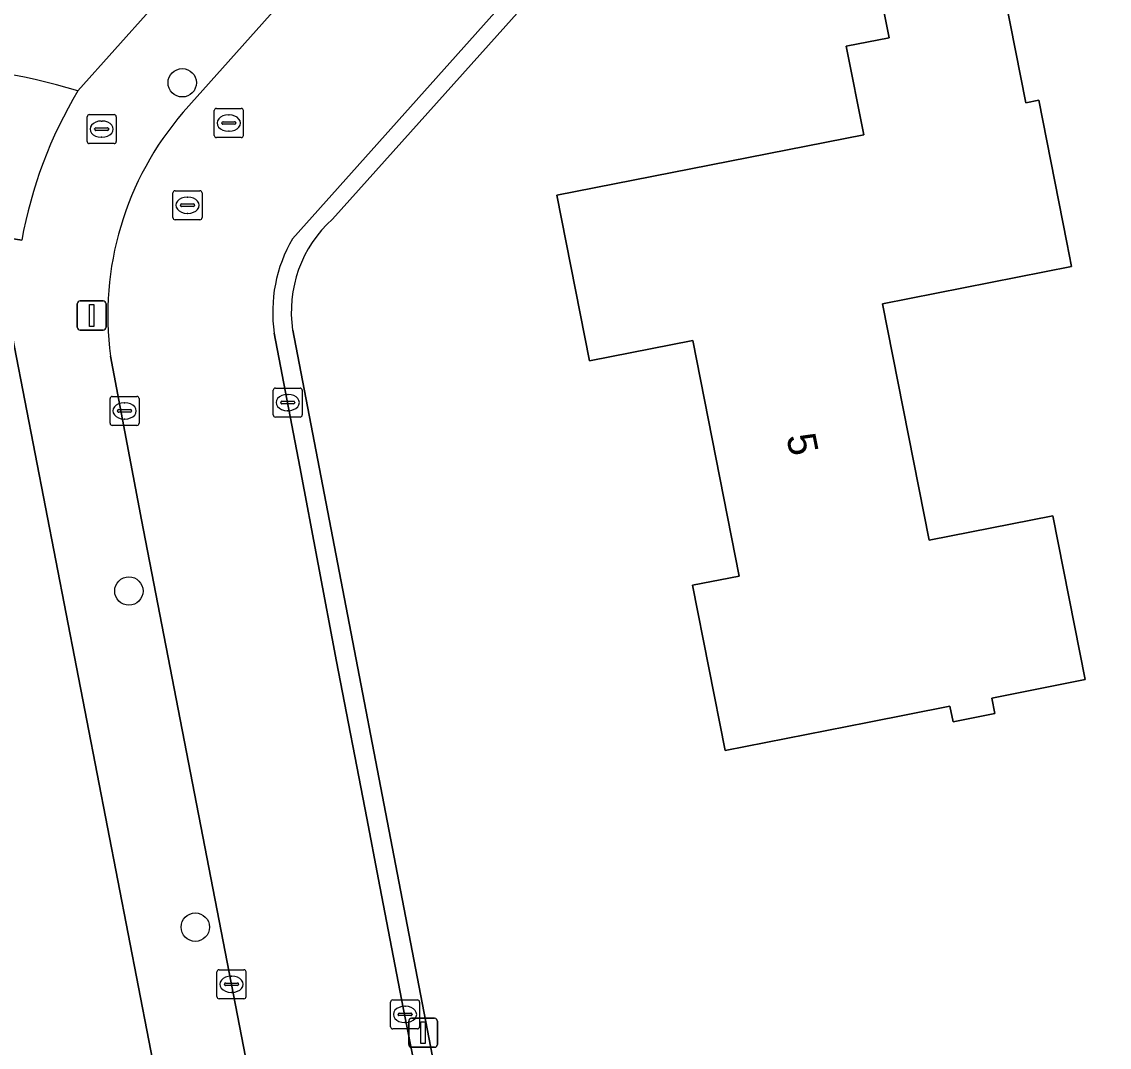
# Model space of a CAD drawing. Extents: x 157648 to 158502, y 379212 to 380938.
# Drawn here: x 158338.43 to 158375.88, y 380216.08 to 380251.41 of the extents above; entities that cross this region are included whole.
import ezdxf

# ---------------------------------------------------------------- set-up
doc = ezdxf.new("R2010")
doc.units = 0
for name, color, linetype in [('IMGEO_Boom', 7, 'Continuous'), ('IMGEO_Brandkraan', 7, 'Continuous'), ('IMGEO_Erf', 7, 'Continuous'), ('IMGEO_Kolk', 7, 'Continuous'), ('IMGEO_Lichtmast', 7, 'Continuous'), ('IMGEO_Pand', 7, 'Continuous'), ('IMGEO_Pand_nummerreeks', 7, 'Continuous'), ('IMGEO_Rijbaan_lokaal_open', 7, 'Continuous'), ('IMGEO_Rioolput', 7, 'Continuous'), ('IMGEO_Voetpad_open', 7, 'Continuous')]:
    doc.layers.add(name, color=color, linetype=linetype)

msp = doc.modelspace()

# ---------------------------------------------------------------- linework, layer by layer
at = {"layer": 'IMGEO_Boom'}
for centre in [(158343.956, 380249.306), (158342.119, 380231.798), (158344.405, 380220.221)]:
    msp.add_circle(centre, 0.489, dxfattribs=at)
at = {"layer": 'IMGEO_Brandkraan'}
for p, q in [((158340.681, 380247.283), (158340.681, 380248.135)), ((158340.756, 380248.209), (158341.608, 380248.209)), ((158341.169, 380247.989), (158341.194, 380247.989)), ((158341.682, 380248.135), (158341.682, 380247.283)), ((158340.94, 380247.703), (158340.94, 380247.715)), ((158341.378, 380247.666), (158340.98, 380247.666)), ((158340.983, 380247.752), (158341.381, 380247.752)), ((158341.424, 380247.715), (158341.424, 380247.703)), ((158341.608, 380247.209), (158340.756, 380247.209)), ((158341.192, 380247.429), (158341.167, 380247.429))]:
    msp.add_line(p, q, dxfattribs=at)
for points in [[(158340.681, 380247.283), (158340.681, 380248.135)], [(158340.756, 380248.209), (158341.608, 380248.209)], [(158341.682, 380248.135), (158341.682, 380247.283)], [(158341.608, 380247.209), (158340.756, 380247.209)]]:
    msp.add_lwpolyline(points, dxfattribs=at)
for centre, radius, start, end in [((158340.758, 380248.133), 0.0765, 91.552, 178.448), ((158340.758, 380248.133), 0.0765, 91.552, 178.448), ((158341.606, 380248.133), 0.0765, 1.552, 88.448), ((158341.606, 380248.133), 0.0765, 1.552, 88.448), ((158340.98, 380247.712), 0.0403, 85.8775, 175.7526), ((158340.977, 380247.702), 0.0366, 178.938, 274.7102), ((158341.381, 380247.709), 0.043, 264.8664, 352.4533), ((158341.385, 380247.714), 0.0386, 1.7309, 96.639), ((158340.758, 380247.285), 0.0765, 181.552, 268.448), ((158340.758, 380247.285), 0.0765, 181.552, 268.448), ((158341.606, 380247.285), 0.0765, 271.552, 358.448), ((158341.606, 380247.285), 0.0765, 271.552, 358.448)]:
    msp.add_arc(centre, radius, start, end, dxfattribs=at)
for centre, major_axis, ratio, start_param, end_param in [((158341.168, 380247.709), (-0.387, 0.002), 0.722429, 4.712389, 7.853982), ((158341.193, 380247.709), (-0.39, 0.002), 0.717154, 1.570796, 4.712389)]:
    msp.add_ellipse(centre, major_axis=major_axis, ratio=ratio, start_param=start_param, end_param=end_param, dxfattribs=at)
at = {"layer": 'IMGEO_Erf'}
for points in [[(158340.365, 380249.033), (158363.297, 380274.662)], [(158429.436, 380221.799), (158397.765, 380250), (158373.398, 380271.696), (158349.129, 380244.613)], [(158352.062, 380168.551), (158337.459, 380243.871)], [(158347.76, 380240.781), (158358.166, 380186.679), (158368.973, 380188.865), (158369.173, 380188.521), (158373.845, 380164.27), (158362.257, 380162.057), (158342.395, 380158.264)]]:
    msp.add_lwpolyline(points, dxfattribs=at)
msp.add_lwpolyline([(158368.072, 380241.691), (158369.676, 380233.548), (158373.945, 380234.39), (158375.057, 380228.746), (158371.841, 380228.112), (158371.947, 380227.576), (158370.505, 380227.29), (158370.398, 380227.828), (158367.562, 380227.27), (158362.656, 380226.303), (158361.534, 380232), (158363.14, 380232.316), (158361.541, 380240.433), (158357.982, 380239.732), (158356.859, 380245.434), (158367.426, 380247.516), (158366.825, 380250.563), (158368.299, 380250.854), (158367.832, 380253.223), (158371.947, 380254.034), (158373.014, 380248.617), (158373.454, 380248.704), (158374.42, 380243.799), (158374.583, 380242.974)], close=True, dxfattribs=at)
for centre, radius, start, end in [((158333, 380223.655), 26.425, 73.8176, 100.1183), ((158352.023, 380241.418), 4.311, 132.1775, 188.5034)]:
    msp.add_arc(centre, radius, start, end, dxfattribs=at)
at = {"layer": 'IMGEO_Kolk'}
for p, q in [((158347.088, 380237.864), (158347.088, 380238.716)), ((158347.163, 380238.79), (158348.015, 380238.79)), ((158347.576, 380238.57), (158347.601, 380238.57)), ((158348.089, 380238.716), (158348.089, 380237.864)), ((158341.469, 380237.577), (158341.469, 380238.429)), ((158341.544, 380238.503), (158342.396, 380238.503)), ((158341.957, 380238.283), (158341.982, 380238.283)), ((158342.47, 380238.429), (158342.47, 380237.577)), ((158347.347, 380238.284), (158347.347, 380238.296)), ((158347.785, 380238.247), (158347.387, 380238.247)), ((158347.39, 380238.333), (158347.788, 380238.333)), ((158347.831, 380238.296), (158347.831, 380238.284)), ((158341.728, 380237.997), (158341.728, 380238.009)), ((158342.166, 380237.96), (158341.768, 380237.96)), ((158341.771, 380238.046), (158342.169, 380238.046)), ((158342.212, 380238.009), (158342.212, 380237.997)), ((158348.015, 380237.79), (158347.163, 380237.79)), ((158347.599, 380238.01), (158347.574, 380238.01)), ((158342.396, 380237.503), (158341.544, 380237.503)), ((158341.98, 380237.723), (158341.955, 380237.723)), ((158345.226, 380218.753), (158346.078, 380218.753)), ((158345.151, 380217.827), (158345.151, 380218.679)), ((158345.639, 380218.533), (158345.664, 380218.533)), ((158346.152, 380218.679), (158346.152, 380217.827)), ((158345.41, 380218.247), (158345.41, 380218.259)), ((158345.848, 380218.21), (158345.45, 380218.21)), ((158345.453, 380218.296), (158345.851, 380218.296)), ((158345.662, 380217.973), (158345.637, 380217.973)), ((158345.894, 380218.259), (158345.894, 380218.247)), ((158346.078, 380217.753), (158345.226, 380217.753)), ((158351.129, 380216.789), (158351.129, 380217.641)), ((158351.204, 380217.715), (158352.056, 380217.715)), ((158352.13, 380217.641), (158352.13, 380216.789)), ((158351.388, 380217.209), (158351.388, 380217.221)), ((158351.431, 380217.258), (158351.829, 380217.258)), ((158351.617, 380217.495), (158351.642, 380217.495)), ((158351.872, 380217.221), (158351.872, 380217.209)), ((158351.826, 380217.172), (158351.428, 380217.172)), ((158351.64, 380216.935), (158351.615, 380216.935)), ((158352.056, 380216.715), (158351.204, 380216.715))]:
    msp.add_line(p, q, dxfattribs=at)
for points in [[(158347.088, 380237.864), (158347.088, 380238.716)], [(158347.163, 380238.79), (158348.015, 380238.79)], [(158348.089, 380238.716), (158348.089, 380237.864)], [(158341.469, 380237.577), (158341.469, 380238.429)], [(158341.544, 380238.503), (158342.396, 380238.503)], [(158342.47, 380238.429), (158342.47, 380237.577)], [(158348.015, 380237.79), (158347.163, 380237.79)], [(158342.396, 380237.503), (158341.544, 380237.503)], [(158345.226, 380218.753), (158346.078, 380218.753)], [(158345.151, 380217.827), (158345.151, 380218.679)], [(158346.152, 380218.679), (158346.152, 380217.827)], [(158346.078, 380217.753), (158345.226, 380217.753)], [(158351.129, 380216.789), (158351.129, 380217.641)], [(158351.204, 380217.715), (158352.056, 380217.715)], [(158352.13, 380217.641), (158352.13, 380216.789)], [(158352.056, 380216.715), (158351.204, 380216.715)]]:
    msp.add_lwpolyline(points, dxfattribs=at)
for centre, radius, start, end in [((158347.165, 380238.714), 0.0765, 91.552, 178.448), ((158347.165, 380238.714), 0.0765, 91.552, 178.448), ((158348.013, 380238.714), 0.0765, 1.552, 88.448), ((158348.013, 380238.714), 0.0765, 1.552, 88.448), ((158341.546, 380238.427), 0.0765, 91.552, 178.448), ((158341.546, 380238.427), 0.0765, 91.552, 178.448), ((158342.394, 380238.427), 0.0765, 1.552, 88.448), ((158342.394, 380238.427), 0.0765, 1.552, 88.448), ((158347.387, 380238.293), 0.0403, 85.8775, 175.7526), ((158347.384, 380238.283), 0.0366, 178.938, 274.7102), ((158347.788, 380238.29), 0.043, 264.8664, 352.4533), ((158347.792, 380238.295), 0.0386, 1.7309, 96.639), ((158341.768, 380238.006), 0.0403, 85.8775, 175.7526), ((158341.765, 380237.996), 0.0366, 178.938, 274.7102), ((158342.169, 380238.003), 0.043, 264.8664, 352.4533), ((158342.173, 380238.008), 0.0386, 1.7309, 96.639), ((158347.165, 380237.866), 0.0765, 181.552, 268.448), ((158347.165, 380237.866), 0.0765, 181.552, 268.448), ((158348.013, 380237.866), 0.0765, 271.552, 358.448), ((158348.013, 380237.866), 0.0765, 271.552, 358.448), ((158341.546, 380237.579), 0.0765, 181.552, 268.448), ((158341.546, 380237.579), 0.0765, 181.552, 268.448), ((158342.394, 380237.579), 0.0765, 271.552, 358.448), ((158342.394, 380237.579), 0.0765, 271.552, 358.448), ((158345.228, 380218.677), 0.0765, 91.552, 178.448), ((158345.228, 380218.677), 0.0765, 91.552, 178.448), ((158346.076, 380218.677), 0.0765, 1.552, 88.448), ((158346.076, 380218.677), 0.0765, 1.552, 88.448), ((158345.45, 380218.256), 0.0403, 85.8775, 175.7526), ((158345.447, 380218.246), 0.0366, 178.938, 274.7102), ((158345.851, 380218.253), 0.043, 264.8664, 352.4533), ((158345.855, 380218.258), 0.0386, 1.7309, 96.639), ((158345.228, 380217.829), 0.0765, 181.552, 268.448), ((158345.228, 380217.829), 0.0765, 181.552, 268.448), ((158346.076, 380217.829), 0.0765, 271.552, 358.448), ((158346.076, 380217.829), 0.0765, 271.552, 358.448), ((158351.206, 380217.639), 0.0765, 91.552, 178.448), ((158351.206, 380217.639), 0.0765, 91.552, 178.448), ((158352.054, 380217.639), 0.0765, 1.552, 88.448), ((158352.054, 380217.639), 0.0765, 1.552, 88.448), ((158351.428, 380217.218), 0.0403, 85.8775, 175.7526), ((158351.425, 380217.208), 0.0366, 178.938, 274.7102), ((158351.829, 380217.215), 0.043, 264.8664, 352.4533), ((158351.833, 380217.22), 0.0386, 1.7309, 96.639), ((158351.206, 380216.791), 0.0765, 181.552, 268.448), ((158351.206, 380216.791), 0.0765, 181.552, 268.448), ((158352.054, 380216.791), 0.0765, 271.552, 358.448), ((158352.054, 380216.791), 0.0765, 271.552, 358.448)]:
    msp.add_arc(centre, radius, start, end, dxfattribs=at)
for centre, major_axis, ratio, start_param, end_param in [((158347.575, 380238.29), (-0.387, 0.002), 0.722429, 4.712389, 7.853982), ((158347.6, 380238.29), (-0.39, 0.002), 0.717154, 1.570796, 4.712389), ((158341.956, 380238.003), (-0.387, 0.002), 0.722429, 4.712389, 7.853982), ((158341.981, 380238.003), (-0.39, 0.002), 0.717154, 1.570796, 4.712389), ((158345.638, 380218.253), (-0.387, 0.002), 0.722429, 4.712389, 7.853982), ((158345.663, 380218.253), (-0.39, 0.002), 0.717154, 1.570796, 4.712389), ((158351.616, 380217.215), (-0.387, 0.002), 0.722429, 4.712389, 7.853982), ((158351.641, 380217.215), (-0.39, 0.002), 0.717154, 1.570796, 4.712389)]:
    msp.add_ellipse(centre, major_axis=major_axis, ratio=ratio, start_param=start_param, end_param=end_param, dxfattribs=at)
at = {"layer": 'IMGEO_Lichtmast'}
for p, q in [((158340.343, 380240.89), (158340.343, 380241.69)), ((158340.343, 380241.69), (158340.343, 380240.89)), ((158340.443, 380241.79), (158341.233, 380241.79)), ((158341.233, 380241.79), (158340.443, 380241.79)), ((158341.333, 380241.69), (158341.333, 380240.89)), ((158341.333, 380240.89), (158341.333, 380241.69)), ((158341.233, 380240.79), (158340.443, 380240.79)), ((158340.443, 380240.79), (158341.233, 380240.79)), ((158351.757, 380216.183), (158351.757, 380216.983)), ((158351.757, 380216.983), (158351.757, 380216.183)), ((158351.857, 380217.083), (158352.647, 380217.083)), ((158352.647, 380217.083), (158351.857, 380217.083)), ((158352.747, 380216.983), (158352.747, 380216.183)), ((158352.747, 380216.183), (158352.747, 380216.983)), ((158352.647, 380216.083), (158351.857, 380216.083)), ((158351.857, 380216.083), (158352.647, 380216.083))]:
    msp.add_line(p, q, dxfattribs=at)
for points in [[(158340.763, 380241.665), (158340.913, 380241.665), (158340.913, 380240.915), (158340.763, 380240.915), (158340.763, 380241.665)], [(158352.177, 380216.958), (158352.327, 380216.958), (158352.327, 380216.208), (158352.177, 380216.208), (158352.177, 380216.958)]]:
    msp.add_lwpolyline(points, dxfattribs=at)
for centre, start, end in [((158340.443, 380241.69), 90, 180), ((158340.443, 380241.69), 90, 180), ((158341.233, 380241.69), 0, 90), ((158341.233, 380241.69), 360, 90), ((158340.443, 380240.89), 180, 270), ((158340.443, 380240.89), 180, 270), ((158341.233, 380240.89), 270, 0), ((158341.233, 380240.89), 270, 0), ((158351.857, 380216.983), 90, 180), ((158351.857, 380216.983), 90, 180), ((158352.647, 380216.983), 0, 90), ((158352.647, 380216.983), 360, 90), ((158351.857, 380216.183), 180, 270), ((158351.857, 380216.183), 180, 270), ((158352.647, 380216.183), 270, 0), ((158352.647, 380216.183), 270, 0)]:
    msp.add_arc(centre, 0.1, start, end, dxfattribs=at)
at = {"layer": 'IMGEO_Pand'}
msp.add_lwpolyline([(158374.583, 380242.974), (158374.42, 380243.799), (158373.454, 380248.704), (158373.014, 380248.617), (158371.947, 380254.034), (158367.832, 380253.223), (158368.299, 380250.854), (158366.825, 380250.563), (158367.426, 380247.516), (158356.859, 380245.434), (158357.982, 380239.732), (158361.541, 380240.433), (158363.14, 380232.316), (158361.534, 380232), (158362.656, 380226.303), (158367.562, 380227.27), (158370.398, 380227.828), (158370.505, 380227.29), (158371.947, 380227.576), (158371.841, 380228.112), (158375.057, 380228.746), (158373.945, 380234.39), (158369.676, 380233.548), (158368.072, 380241.691)], close=True, dxfattribs=at)
at = {"layer": 'IMGEO_Rijbaan_lokaal_open'}
for points in [[(158347.759, 380243.933), (158372.911, 380272.081), (158374.084, 380273.393), (158365.367, 380281.05)], [(158365.354, 380272.214), (158343.989, 380248.29)], [(158337.459, 380243.871), (158337.415, 380244.044), (158338.429, 380243.882)], [(158348.002, 380236.082), (158347.127, 380240.686)], [(158341.491, 380239.885), (158342.556, 380234.248), (158350.498, 380193.223), (158351.536, 380187.815), (158354.388, 380173.111), (158356.61, 380161.656), (158362.13, 380162.73), (158361.286, 380167.174), (158359.368, 380177.042), (158359.157, 380178.197), (158358.119, 380183.611), (158357.551, 380186.555), (158353.824, 380205.882), (158352.784, 380211.321), (158351.565, 380217.443), (158350.715, 380221.864), (158350.316, 380223.973), (158349.267, 380229.375), (158348.002, 380236.082)]]:
    msp.add_lwpolyline(points, dxfattribs=at)
for centre, radius, start, end in [((158333, 380223.655), 26.425, 73.8176, 100.1183), ((158353.463, 380241.171), 15.276, 149.025, 169.7776), ((158352.057, 380241.319), 10.663, 139.1693, 187.7264), ((158352.026, 380241.417), 4.954, 149.4809, 188.4903)]:
    msp.add_arc(centre, radius, start, end, dxfattribs=at)
at = {"layer": 'IMGEO_Rioolput'}
for p, q in [((158345.059, 380247.494), (158345.059, 380248.346)), ((158345.134, 380248.42), (158345.986, 380248.42)), ((158346.06, 380248.346), (158346.06, 380247.494)), ((158345.318, 380247.914), (158345.318, 380247.926)), ((158345.361, 380247.963), (158345.759, 380247.963)), ((158345.547, 380248.2), (158345.572, 380248.2)), ((158345.802, 380247.926), (158345.802, 380247.914)), ((158345.756, 380247.877), (158345.358, 380247.877)), ((158345.57, 380247.64), (158345.545, 380247.64)), ((158345.986, 380247.42), (158345.134, 380247.42)), ((158343.637, 380244.662), (158343.637, 380245.514)), ((158343.712, 380245.588), (158344.564, 380245.588)), ((158344.125, 380245.368), (158344.15, 380245.368)), ((158344.638, 380245.514), (158344.638, 380244.662)), ((158343.896, 380245.082), (158343.896, 380245.094)), ((158344.334, 380245.045), (158343.936, 380245.045)), ((158343.939, 380245.131), (158344.337, 380245.131)), ((158344.38, 380245.094), (158344.38, 380245.082)), ((158344.564, 380244.588), (158343.712, 380244.588)), ((158344.148, 380244.808), (158344.123, 380244.808))]:
    msp.add_line(p, q, dxfattribs=at)
for points in [[(158345.059, 380247.494), (158345.059, 380248.346)], [(158345.134, 380248.42), (158345.986, 380248.42)], [(158346.06, 380248.346), (158346.06, 380247.494)], [(158345.986, 380247.42), (158345.134, 380247.42)], [(158343.637, 380244.662), (158343.637, 380245.514)], [(158343.712, 380245.588), (158344.564, 380245.588)], [(158344.638, 380245.514), (158344.638, 380244.662)], [(158344.564, 380244.588), (158343.712, 380244.588)]]:
    msp.add_lwpolyline(points, dxfattribs=at)
for centre, radius, start, end in [((158345.136, 380248.344), 0.0765, 91.552, 178.448), ((158345.136, 380248.344), 0.0765, 91.552, 178.448), ((158345.984, 380248.344), 0.0765, 1.552, 88.448), ((158345.984, 380248.344), 0.0765, 1.552, 88.448), ((158345.358, 380247.923), 0.0403, 85.8775, 175.7526), ((158345.355, 380247.913), 0.0366, 178.938, 274.7102), ((158345.759, 380247.92), 0.043, 264.8664, 352.4533), ((158345.763, 380247.925), 0.0386, 1.7309, 96.639), ((158345.136, 380247.496), 0.0765, 181.552, 268.448), ((158345.136, 380247.496), 0.0765, 181.552, 268.448), ((158345.984, 380247.496), 0.0765, 271.552, 358.448), ((158345.984, 380247.496), 0.0765, 271.552, 358.448), ((158343.714, 380245.512), 0.0765, 91.552, 178.448), ((158343.714, 380245.512), 0.0765, 91.552, 178.448), ((158344.562, 380245.512), 0.0765, 1.552, 88.448), ((158344.562, 380245.512), 0.0765, 1.552, 88.448), ((158343.936, 380245.091), 0.0403, 85.8775, 175.7526), ((158343.933, 380245.081), 0.0366, 178.938, 274.7102), ((158344.337, 380245.088), 0.043, 264.8664, 352.4533), ((158344.341, 380245.093), 0.0386, 1.7309, 96.639), ((158343.714, 380244.664), 0.0765, 181.552, 268.448), ((158343.714, 380244.664), 0.0765, 181.552, 268.448), ((158344.562, 380244.664), 0.0765, 271.552, 358.448), ((158344.562, 380244.664), 0.0765, 271.552, 358.448)]:
    msp.add_arc(centre, radius, start, end, dxfattribs=at)
for centre, major_axis, ratio, start_param, end_param in [((158345.546, 380247.92), (-0.387, 0.002), 0.722429, 4.712389, 7.853982), ((158345.571, 380247.92), (-0.39, 0.002), 0.717154, 1.570796, 4.712389), ((158344.124, 380245.088), (-0.387, 0.002), 0.722429, 4.712389, 7.853982), ((158344.149, 380245.088), (-0.39, 0.002), 0.717154, 1.570796, 4.712389)]:
    msp.add_ellipse(centre, major_axis=major_axis, ratio=ratio, start_param=start_param, end_param=end_param, dxfattribs=at)
at = {"layer": 'IMGEO_Voetpad_open'}
for points in [[(158363.297, 380274.662), (158340.365, 380249.033)], [(158375.361, 380274.822), (158374.084, 380273.393), (158372.911, 380272.081), (158347.759, 380243.933)], [(158349.129, 380244.613), (158373.398, 380271.696), (158375.706, 380274.271)], [(158343.989, 380248.29), (158365.354, 380272.214)], [(158338.429, 380243.882), (158337.415, 380244.044), (158337.459, 380243.871), (158352.062, 380168.551), (158353.342, 380168.614)], [(158347.127, 380240.686), (158348.002, 380236.082), (158349.267, 380229.375), (158350.316, 380223.973), (158350.715, 380221.864), (158351.565, 380217.443), (158352.784, 380211.321), (158353.824, 380205.882), (158357.551, 380186.555), (158358.166, 380186.679), (158347.76, 380240.781)], [(158354.388, 380173.111), (158351.536, 380187.815), (158350.498, 380193.223), (158342.556, 380234.248), (158341.491, 380239.885)]]:
    msp.add_lwpolyline(points, dxfattribs=at)
for centre, radius, start, end in [((158353.463, 380241.171), 15.276, 149.025, 169.7776), ((158352.057, 380241.319), 10.663, 139.1693, 187.7264), ((158352.023, 380241.418), 4.311, 132.1775, 188.5034), ((158352.026, 380241.417), 4.954, 149.4809, 188.4903)]:
    msp.add_arc(centre, radius, start, end, dxfattribs=at)

# ---------------------------------------------------------------- texts
at = {"layer": 'IMGEO_Pand_nummerreeks'}
msp.add_text('5', height=1, rotation=281.1438, dxfattribs=at).set_placement((158364.76, 380237.131))

doc.saveas('drawing.dxf')
